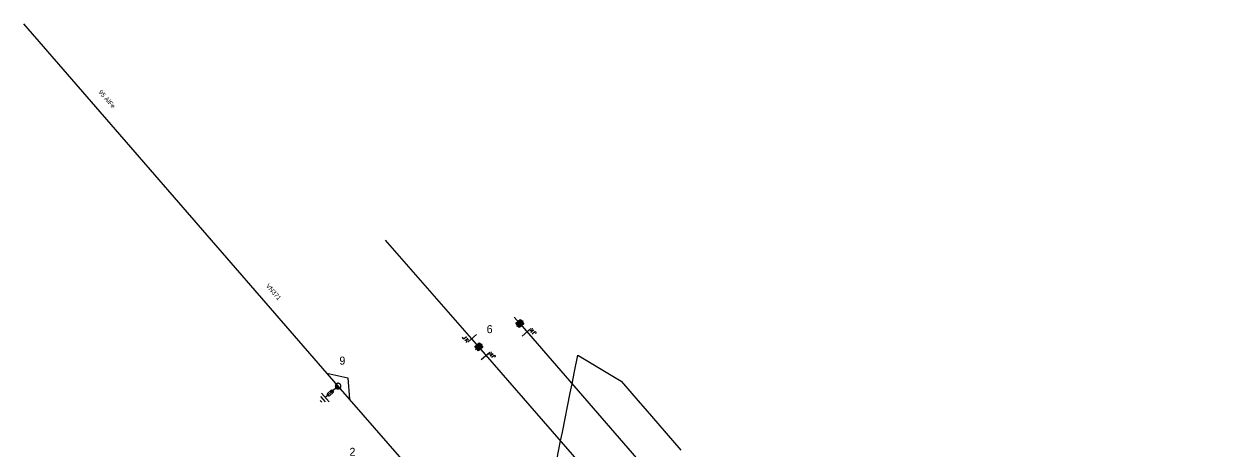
# Model space of a CAD drawing. Extents: x -540879 to -537255, y -1184046 to -1180016.
# Drawn here: x -537823.3 to -537563.1, y -1180154.3 to -1180061.6 of the extents above; entities that cross this region are included whole.
import ezdxf

# ---------------------------------------------------------------- set-up
doc = ezdxf.new("R2010")
doc.units = 0
for name, color, linetype in [('Vrstva 1', 7, 'Continuous'), ('Vrstva 12', 7, 'Continuous'), ('Vrstva 13', 7, 'Continuous'), ('Vrstva 14', 7, 'Continuous'), ('Vrstva 15', 7, 'Continuous'), ('Vrstva 16', 7, 'Continuous'), ('Vrstva 18', 7, 'Continuous'), ('Vrstva 2', 7, 'Continuous'), ('Vrstva 3', 7, 'Continuous'), ('Vrstva 35', 7, 'Continuous')]:
    doc.layers.add(name, color=color, linetype=linetype)

# ---------------------------------------------------------------- blocks, each defined once
blk = doc.blocks.new('VN840')
at = {"layer": 'Vrstva 15'}
for points in [[(-0.01, 1.41), (-0.01, -1.09)], [(-1.51, -1.24), (-1.51, -1.15)], [(-1.48, -1.35), (-1.51, -1.24)], [(-1.33, -1.42), (-1.48, -1.35)], [(-1.27, -1.42), (-1.33, -1.42)], [(-1.13, -1.35), (-1.27, -1.42)], [(-1.09, -1.24), (-1.13, -1.35)], [(-1.09, -0.59), (-1.09, -1.24)], [(-0.68, -0.59), (-0.68, -1.42)], [(-0.68, -1.11), (-0.27, -0.59)], [(-0.54, -0.94), (-0.2, -1.42)]]:
    blk.add_lwpolyline(points, dxfattribs=at)
blk = doc.blocks.new('VN860')
at = {"layer": 'Vrstva 15'}
for points in [[(-3.74, 0), (0.01, 2.82)], [(0.01, 2.82), (3.76, 0)]]:
    blk.add_lwpolyline(points, dxfattribs=at)
blk = doc.blocks.new('VN440')
at = {"layer": 'Vrstva 2'}
for points in [[(1.22, 0), (1.21, 0.13), (1.19, 0.25), (1.16, 0.38), (1.11, 0.5), (1.05, 0.61), (0.98, 0.72), (0.9, 0.82), (0.81, 0.91), (0.71, 0.99), (0.6, 1.06), (0.49, 1.12), (0.37, 1.16), (0.25, 1.2), (0.12, 1.22), (-0.01, 1.22), (-0.14, 1.22), (-0.26, 1.2), (-0.39, 1.16), (-0.51, 1.12), (-0.62, 1.06), (-0.73, 0.99), (-0.83, 0.91), (-0.92, 0.82), (-1, 0.72), (-1.07, 0.61), (-1.13, 0.5), (-1.18, 0.38), (-1.21, 0.25), (-1.23, 0.13), (-1.24, 0), (-1.23, -0.13), (-1.21, -0.26), (-1.18, -0.38), (-1.13, -0.5), (-1.07, -0.62), (-1, -0.73), (-0.92, -0.83), (-0.83, -0.92), (-0.73, -1), (-0.62, -1.07), (-0.51, -1.13), (-0.39, -1.17), (-0.26, -1.2), (-0.14, -1.23), (-0.01, -1.23), (0.12, -1.23), (0.25, -1.2), (0.37, -1.17), (0.49, -1.13), (0.6, -1.07), (0.71, -1), (0.81, -0.92), (0.9, -0.83), (0.98, -0.73), (1.05, -0.62), (1.11, -0.5), (1.16, -0.38), (1.19, -0.26), (1.21, -0.13), (1.22, 0)], [(-1.24, 0), (1.22, 0)], [(-1.18, -0.34), (1.1, -0.34)], [(-1.01, -0.63), (0.97, -0.63)], [(-0.74, -0.92), (0.68, -0.92)]]:
    blk.add_lwpolyline(points, dxfattribs=at)
blk = doc.blocks.new('VN820')
at = {"layer": 'Vrstva 13'}
for points in [[(0, 0), (0, -2.1)], [(-0.32, -1.63), (0.34, -1.63)], [(-0.32, -2.95), (-0.32, -1.63)], [(0, -2.1), (-0.12, -1.86)], [(0, -2.1), (0.12, -1.86)], [(0.34, -1.63), (0.34, -2.95)], [(0.34, -2.95), (-0.32, -2.95)], [(0, -2.95), (0, -3.75)]]:
    blk.add_lwpolyline(points, dxfattribs=at)
blk = doc.blocks.new('VN810')
at = {"layer": 'Vrstva 14'}
for points in [[(0, -1.25), (0, -3.75)], [(1.25, -3.75), (-1.25, -3.75)], [(0.77, -4.37), (-0.8, -4.37)], [(0, -5), (-0.25, -5)], [(0.27, -5), (0, -5)]]:
    blk.add_lwpolyline(points, dxfattribs=at)
blk = doc.blocks.new('VN470')
at = {"layer": 'Vrstva 2'}
for points in [[(-1.23, 1.22), (1.23, 1.22)], [(-1.23, -1.23), (-1.23, 1.22)], [(-0.92, 0.9), (0.92, 0.9)], [(-0.92, -0.95), (-0.92, 0.9)], [(-0.61, 0.61), (0.61, 0.61)], [(-0.61, -0.62), (-0.61, 0.61)], [(-0.31, -0.27), (-0.31, 0.34)], [(-0.31, 0.34), (0.31, 0.34)], [(0, 1.22), (0, 1.97)], [(0.31, 0.34), (0.31, -0.27)], [(0.61, 0.61), (0.61, -0.62)], [(0.92, 0.9), (0.92, -0.95)], [(1.23, 1.22), (1.23, -1.23)], [(1.23, -1.23), (-1.23, -1.23)], [(0.92, -0.95), (-0.92, -0.95)], [(0.61, -0.62), (-0.61, -0.62)], [(0.31, -0.27), (-0.31, -0.27)], [(0, -1.23), (0, -1.98)]]:
    blk.add_lwpolyline(points, dxfattribs=at)

msp = doc.modelspace()

# ---------------------------------------------------------------- linework, layer by layer
at = {"layer": 'Vrstva 1'}
for points in [[(-537716.9, -1180183.95), (-537754.62, -1180140.72), (-537823.35, -1180061.61)], [(-537534.01, -1180350.75), (-537569.87, -1180309.27), (-537631.69, -1180238), (-537723.88, -1180132.14), (-537744.24, -1180108.87)], [(-537716.13, -1180125.67), (-537714.92, -1180127.04), (-537625.68, -1180229.9), (-537553.13, -1180313.31), (-537526.37, -1180344.35)]]:
    msp.add_lwpolyline(points, dxfattribs=at)
at = {"layer": 'Vrstva 35'}
msp.add_lwpolyline([(-537706.82, -1180156.82), (-537705.99, -1180152.69), (-537705.6, -1180150.76), (-537703.87, -1180142.18), (-537703.48, -1180140.23), (-537702.93, -1180137.5), (-537702.22, -1180133.98), (-537692.74, -1180139.64), (-537691.3, -1180141.3), (-537689.09, -1180143.84), (-537687.5, -1180145.67), (-537679.68, -1180154.68)], dxfattribs=at)

# ---------------------------------------------------------------- block references
at = {"layer": 'Vrstva 13'}
for name, p, xscale, yscale, rotation in [('VN470', (-537714.92, -1180127.04), 0.49999999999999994, 0.5000000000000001, -48.9125889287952), ('VN470', (-537723.88, -1180132.14), 0.5, 0.5, -48.98268055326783), ('VN440', (-537754.62, -1180140.72), 0.49999999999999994, 0.49999999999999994, -48.770344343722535)]:
    msp.add_blockref(name, p, dxfattribs=dict(at, xscale=xscale, yscale=yscale, rotation=rotation))
at = {"layer": 'Vrstva 15', "rotation": -48.770344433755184}
msp.add_blockref('VN810', (-537754.62, -1180140.72), dxfattribs=at)
at = {"layer": 'Vrstva 16', "rotation": -48.770344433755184}
msp.add_blockref('VN820', (-537754.62, -1180140.72), dxfattribs=at)
at = {"layer": 'Vrstva 18'}
for name, p, rotation in [('VN840', (-537725.41, -1180130.39), -48.81407483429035), ('VN840', (-537713.36, -1180128.85), 130.849371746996), ('VN840', (-537722.27, -1180133.99), 131.0515372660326), ('VN860', (-537754.62, -1180140.72), -48.94225284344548)]:
    msp.add_blockref(name, p, dxfattribs=dict(at, rotation=rotation))

# ---------------------------------------------------------------- texts
at = {"layer": 'Vrstva 12'}
msp.add_text('2', height=1.75, dxfattribs=at).set_placement((-537752.14, -1180155.94))
at = {"layer": 'Vrstva 14'}
for s, p in [('6', (-537722.16, -1180129.16)), ('9', (-537754.35, -1180136.03))]:
    msp.add_text(s, height=1.75, dxfattribs=at).set_placement(p)
at = {"layer": 'Vrstva 2'}
msp.add_text('95 AlFe', height=1, rotation=310.741, dxfattribs=at).set_placement((-537807.09, -1180076.57))
at = {"layer": 'Vrstva 3'}
msp.add_text('VN371', height=1, rotation=310.741, dxfattribs=at).set_placement((-537770.5, -1180118.87))

doc.saveas('drawing.dxf')
